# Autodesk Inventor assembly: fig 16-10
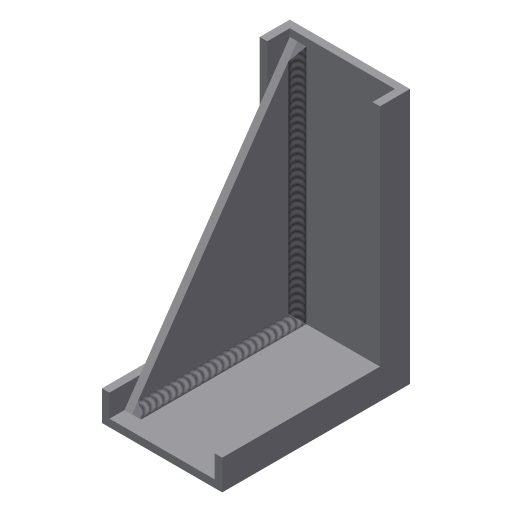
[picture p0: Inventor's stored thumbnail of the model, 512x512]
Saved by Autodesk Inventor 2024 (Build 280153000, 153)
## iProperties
Shininess: 64.0
Length Units: 11269
Angle Units: 11279
Time Units: 11290
Mass Units: 11283
Length Display Precision: 3
Angle Display Precision: 2
Compacted: True
Created: 2003-01
Part Number: fig 16-10
Document SubType Name: Weldment
Designer: Owner
Density: 0.0
Volumn: 0.0
Area: 0.0
PropertySet Name: Model Information
Control State: 0
Master: False
Checked Out: False
Author: Owner
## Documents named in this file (3)
- D:\PROJECTS\Project 2023\RESOURCES INVENTOR 2024\RESOURCES INVENTOR 2024\Inventor_2023_Part\Inventor_2024_Part\c16_Inv_2024_prt\fig 16-10\fig 16-10.iam
- D:\PROJECTS\Project 2023\RESOURCES INVENTOR 2024\RESOURCES INVENTOR 2024\Inventor_2023_Part\Inventor_2024_Part\c16_Inv_2024_prt\fig 16-10\Bracket-1.ipt
- D:\PROJECTS\Project 2023\RESOURCES INVENTOR 2024\RESOURCES INVENTOR 2024\Inventor_2023_Part\Inventor_2024_Part\c16_Inv_2024_prt\fig 16-10\Bracket-plate.ipt
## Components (2 placed, 2 different names)
1. Bracket-1:1 — Mate:1, Mate:2
2. Bracket-plate:1 — Mate:1, Mate:2
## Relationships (2: Mate 2)
- Mate:1: Bracket-1:1 ↔ Bracket-plate:1
- Mate:2: Bracket-1:1 ↔ Bracket-plate:1
